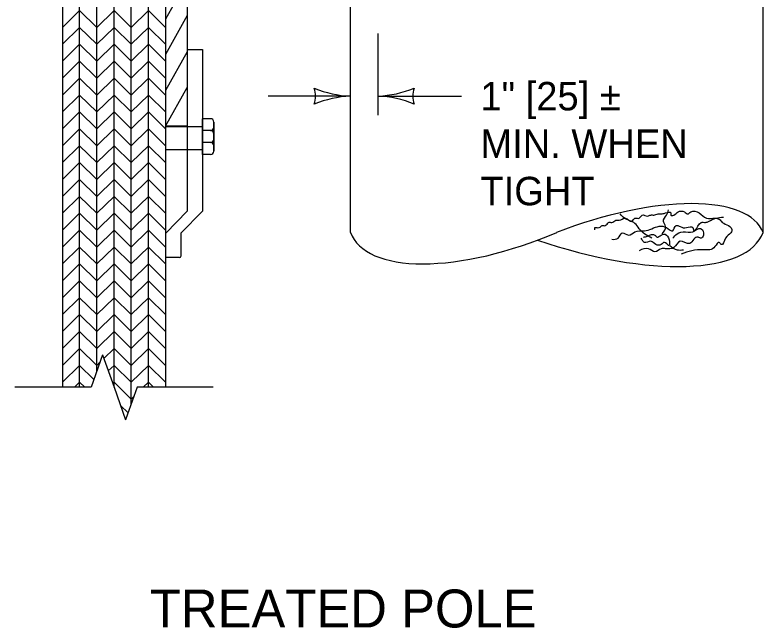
# Model space of a CAD drawing. Extents: x 49991.4 to 50021, y 49987.6 to 50011.4.
# Drawn here: x 50010.201 to 50011.777, y 49992.457 to 49993.749 of the extents above; entities that cross this region are included whole.
import ezdxf

# ---------------------------------------------------------------- set-up
doc = ezdxf.new("R2010")
doc.units = 0
for name, color, linetype in [('Level 1', 7, 'Continuous'), ('Level 2', 7, 'Continuous'), ('Level 3', 7, 'Continuous'), ('Level 4', 7, 'Continuous'), ('Level 6', 7, 'Continuous')]:
    doc.layers.add(name, color=color, linetype=linetype)

msp = doc.modelspace()

# ---------------------------------------------------------------- linework, layer by layer
at = {"layer": 'Level 1'}
for p, q in [((50010.3733, 49992.9985), (50010.3733, 49995.0328)), ((50010.3009, 49994.9995), (50010.3009, 49992.9641)), ((50010.3371, 49992.9641), (50010.3371, 49994.9995)), ((50010.4095, 49992.9641), (50010.4095, 49995.0012)), ((50010.4819, 49992.9641), (50010.4819, 49994.9995)), ((50010.5181, 49994.9995), (50010.5181, 49992.9641)), ((50010.4457, 49992.9286), (50010.4457, 49994.9629)), ((50010.9074, 49993.2905), (50010.9074, 49994.7281)), ((50010.3733, 49992.9985), (50010.3733, 49994.5768)), ((50010.4457, 49992.9641), (50010.4457, 49994.5768)), ((50010.5644, 49993.6762), (50010.5644, 49994.0098)), ((50010.5186, 49993.7404), (50010.5651, 49993.8234)), ((50010.3009, 49993.7224), (50010.3371, 49993.758)), ((50010.3733, 49993.7224), (50010.3371, 49993.758)), ((50010.3733, 49993.7224), (50010.4095, 49993.758)), ((50010.4457, 49993.7224), (50010.4095, 49993.758)), ((50010.4457, 49993.7224), (50010.4819, 49993.758)), ((50010.5181, 49993.7224), (50010.4819, 49993.758)), ((50010.5186, 49993.6657), (50010.5646, 49993.7479)), ((50011.7765, 49993.2905), (50011.7765, 49993.7455)), ((50010.3009, 49993.6868), (50010.3371, 49993.7224)), ((50010.3733, 49993.6868), (50010.3371, 49993.7224)), ((50010.3733, 49993.6868), (50010.4095, 49993.7224)), ((50010.4457, 49993.6868), (50010.4095, 49993.7224)), ((50010.4457, 49993.6868), (50010.4819, 49993.7224)), ((50010.5181, 49993.6868), (50010.4819, 49993.7224)), ((50010.3009, 49993.6512), (50010.3371, 49993.6868)), ((50010.3733, 49993.6512), (50010.3371, 49993.6868)), ((50010.3733, 49993.6512), (50010.4095, 49993.6868)), ((50010.4457, 49993.6512), (50010.4095, 49993.6868)), ((50010.4457, 49993.6512), (50010.4819, 49993.6868)), ((50010.5181, 49993.6512), (50010.4819, 49993.6868)), ((50010.5184, 49993.5901), (50010.564, 49993.6715)), ((50010.5636, 49993.6762), (50010.5636, 49993.3914)), ((50010.5644, 49993.6762), (50010.5957, 49993.6762)), ((50010.5957, 49993.6762), (50010.5957, 49993.3914)), ((50010.3009, 49993.6156), (50010.3371, 49993.6512)), ((50010.3733, 49993.6156), (50010.3371, 49993.6512)), ((50010.3733, 49993.6156), (50010.4095, 49993.6512)), ((50010.4457, 49993.6156), (50010.4095, 49993.6512)), ((50010.4457, 49993.6156), (50010.4819, 49993.6512)), ((50010.5181, 49993.6156), (50010.4819, 49993.6512)), ((50010.3009, 49993.58), (50010.3371, 49993.6156)), ((50010.3733, 49993.58), (50010.3371, 49993.6156)), ((50010.3733, 49993.58), (50010.4095, 49993.6156)), ((50010.4457, 49993.58), (50010.4095, 49993.6156)), ((50010.4457, 49993.58), (50010.4819, 49993.6156)), ((50010.5181, 49993.58), (50010.4819, 49993.6156)), ((50010.5181, 49993.5146), (50010.5634, 49993.5955)), ((50010.3009, 49993.5444), (50010.3371, 49993.58)), ((50010.3733, 49993.5444), (50010.3371, 49993.58)), ((50010.3733, 49993.5444), (50010.4095, 49993.58)), ((50010.4457, 49993.5444), (50010.4095, 49993.58)), ((50010.4457, 49993.5444), (50010.4819, 49993.58)), ((50010.5181, 49993.5444), (50010.4819, 49993.58)), ((50010.3009, 49993.5088), (50010.3371, 49993.5444)), ((50010.3733, 49993.5088), (50010.3371, 49993.5444)), ((50010.3733, 49993.5088), (50010.4095, 49993.5444)), ((50010.4457, 49993.5088), (50010.4095, 49993.5444)), ((50010.4457, 49993.5088), (50010.4819, 49993.5444)), ((50010.5181, 49993.5088), (50010.4819, 49993.5444)), ((50010.5956, 49993.5301), (50010.5956, 49993.4546)), ((50010.6125, 49993.5301), (50010.5956, 49993.5301)), ((50010.5959, 49993.4546), (50010.5959, 49993.5301)), ((50010.6128, 49993.5301), (50010.5962, 49993.5301)), ((50010.6196, 49993.5231), (50010.6196, 49993.4616)), ((50010.6199, 49993.4616), (50010.6199, 49993.5231)), ((50010.3009, 49993.4732), (50010.3371, 49993.5088)), ((50010.3733, 49993.4732), (50010.3371, 49993.5088)), ((50010.3733, 49993.4732), (50010.4095, 49993.5088)), ((50010.4457, 49993.4732), (50010.4095, 49993.5088)), ((50010.4457, 49993.4732), (50010.4819, 49993.5088)), ((50010.5181, 49993.4732), (50010.4819, 49993.5088)), ((50010.5181, 49993.5151), (50010.5636, 49993.5151)), ((50010.6196, 49993.5049), (50010.5956, 49993.5049)), ((50010.6199, 49993.5049), (50010.5959, 49993.5049)), ((50010.3009, 49993.4376), (50010.3371, 49993.4732)), ((50010.3733, 49993.4376), (50010.3371, 49993.4732)), ((50010.3733, 49993.4376), (50010.4095, 49993.4732)), ((50010.4457, 49993.4376), (50010.4095, 49993.4732)), ((50010.4457, 49993.4376), (50010.4819, 49993.4732)), ((50010.5181, 49993.4376), (50010.4819, 49993.4732)), ((50010.6196, 49993.4798), (50010.5956, 49993.4798)), ((50010.6199, 49993.4798), (50010.5959, 49993.4798)), ((50010.6128, 49993.4546), (50010.5959, 49993.4546)), ((50010.6125, 49993.4546), (50010.5959, 49993.4546)), ((50010.3009, 49993.402), (50010.3371, 49993.4376)), ((50010.3733, 49993.402), (50010.3371, 49993.4376)), ((50010.3733, 49993.402), (50010.4095, 49993.4376)), ((50010.4457, 49993.402), (50010.4095, 49993.4376)), ((50010.4457, 49993.402), (50010.4819, 49993.4376)), ((50010.5181, 49993.402), (50010.4819, 49993.4376)), ((50010.3009, 49993.3664), (50010.3371, 49993.402)), ((50010.3733, 49993.3664), (50010.3371, 49993.402)), ((50010.3733, 49993.3664), (50010.4095, 49993.402)), ((50010.4457, 49993.3664), (50010.4095, 49993.402)), ((50010.4457, 49993.3664), (50010.4819, 49993.402)), ((50010.5181, 49993.3664), (50010.4819, 49993.402)), ((50010.5636, 49993.3914), (50010.5636, 49993.3352)), ((50010.5957, 49993.3914), (50010.5957, 49993.3352)), ((50010.3009, 49993.3308), (50010.3371, 49993.3664)), ((50010.3733, 49993.3308), (50010.3371, 49993.3664)), ((50010.3733, 49993.3308), (50010.4095, 49993.3664)), ((50010.4457, 49993.3308), (50010.4095, 49993.3664)), ((50010.4457, 49993.3308), (50010.4819, 49993.3664)), ((50010.5181, 49993.3308), (50010.4819, 49993.3664)), ((50010.5185, 49993.2892), (50010.5636, 49993.3352)), ((50010.5506, 49993.2892), (50010.5957, 49993.3352)), ((50010.3009, 49993.2952), (50010.3371, 49993.3308)), ((50010.3733, 49993.2952), (50010.3371, 49993.3308)), ((50010.3733, 49993.2952), (50010.4095, 49993.3308)), ((50010.4457, 49993.2952), (50010.4095, 49993.3308)), ((50010.4457, 49993.2952), (50010.4819, 49993.3308)), ((50010.5181, 49993.2952), (50010.4819, 49993.3308)), ((50010.3009, 49993.2596), (50010.3371, 49993.2952)), ((50010.3733, 49993.2596), (50010.3371, 49993.2952)), ((50010.3733, 49993.2596), (50010.4095, 49993.2952)), ((50010.4457, 49993.2596), (50010.4095, 49993.2952)), ((50010.4457, 49993.2596), (50010.4819, 49993.2952)), ((50010.5181, 49993.2596), (50010.4819, 49993.2952)), ((50010.5506, 49993.2892), (50010.5506, 49993.2409)), ((50010.3009, 49993.224), (50010.3371, 49993.2596)), ((50010.3733, 49993.224), (50010.3371, 49993.2596)), ((50010.3733, 49993.224), (50010.4095, 49993.2596)), ((50010.4457, 49993.224), (50010.4095, 49993.2596)), ((50010.4457, 49993.224), (50010.4819, 49993.2596)), ((50010.5181, 49993.224), (50010.4819, 49993.2596)), ((50010.5471, 49993.2373), (50010.5185, 49993.2373)), ((50010.3009, 49993.1884), (50010.3371, 49993.224)), ((50010.3733, 49993.1884), (50010.3371, 49993.224)), ((50010.3733, 49993.1884), (50010.4095, 49993.224)), ((50010.4457, 49993.1884), (50010.4095, 49993.224)), ((50010.4457, 49993.1884), (50010.4819, 49993.224)), ((50010.5181, 49993.1884), (50010.4819, 49993.224)), ((50010.3009, 49993.1528), (50010.3371, 49993.1884)), ((50010.3733, 49993.1528), (50010.3371, 49993.1884)), ((50010.3733, 49993.1528), (50010.4095, 49993.1884)), ((50010.4457, 49993.1528), (50010.4095, 49993.1884)), ((50010.4457, 49993.1528), (50010.4819, 49993.1884)), ((50010.5181, 49993.1528), (50010.4819, 49993.1884)), ((50010.3009, 49993.1172), (50010.3371, 49993.1528)), ((50010.3733, 49993.1172), (50010.3371, 49993.1528)), ((50010.3733, 49993.1172), (50010.4095, 49993.1528)), ((50010.4457, 49993.1172), (50010.4095, 49993.1528)), ((50010.4457, 49993.1172), (50010.4819, 49993.1528)), ((50010.5181, 49993.1172), (50010.4819, 49993.1528)), ((50010.3009, 49993.0816), (50010.3371, 49993.1172)), ((50010.3733, 49993.0816), (50010.3371, 49993.1172)), ((50010.3733, 49993.0816), (50010.4095, 49993.1172)), ((50010.4457, 49993.0816), (50010.4095, 49993.1172)), ((50010.4457, 49993.0816), (50010.4819, 49993.1172)), ((50010.5181, 49993.0816), (50010.4819, 49993.1172)), ((50010.3009, 49993.046), (50010.3371, 49993.0816)), ((50010.3733, 49993.046), (50010.3371, 49993.0816)), ((50010.3733, 49993.046), (50010.4095, 49993.0816)), ((50010.4457, 49993.046), (50010.4095, 49993.0816)), ((50010.4457, 49993.046), (50010.4819, 49993.0816)), ((50010.5181, 49993.046), (50010.4819, 49993.0816)), ((50010.3009, 49993.0104), (50010.3371, 49993.046)), ((50010.3733, 49993.0104), (50010.3371, 49993.046)), ((50010.3881, 49993.025), (50010.4095, 49993.046)), ((50010.4457, 49993.0104), (50010.4095, 49993.046)), ((50010.4457, 49993.0104), (50010.4819, 49993.046)), ((50010.5181, 49993.0104), (50010.4819, 49993.046)), ((50010.3733, 49993.0104), (50010.3798, 49993.0168)), ((50010.3009, 49992.9748), (50010.3371, 49993.0104)), ((50010.3671, 49992.9809), (50010.3371, 49993.0104)), ((50010.3975, 49992.9986), (50010.4095, 49993.0104)), ((50010.4457, 49992.9748), (50010.4095, 49993.0104)), ((50010.4457, 49992.9748), (50010.4819, 49993.0104)), ((50010.5181, 49992.9748), (50010.4819, 49993.0104)), ((50010.3262, 49992.9641), (50010.3371, 49992.9748)), ((50010.348, 49992.9641), (50010.3371, 49992.9748)), ((50010.4068, 49992.9722), (50010.4095, 49992.9748)), ((50010.4457, 49992.9392), (50010.4095, 49992.9748)), ((50010.471, 49992.9641), (50010.4819, 49992.9748)), ((50010.4928, 49992.9641), (50010.4819, 49992.9748)), ((50010.4457, 49992.9392), (50010.4515, 49992.9449)), ((50010.4391, 49992.9101), (50010.4234, 49992.9256))]:
    msp.add_line(p, q, dxfattribs=at)
for centre, radius, start, end in [((50010.6125, 49993.5231), 0.00703, 0, 90), ((50010.6128, 49993.5231), 0.00703, 0, 90), ((50010.6125, 49993.512), 0.00703, 270, 0), ((50010.6125, 49993.4979), 0.00703, 0, 90), ((50010.6128, 49993.512), 0.00703, 270, 0), ((50010.6128, 49993.4979), 0.00703, 0, 90), ((50010.6125, 49993.4868), 0.00703, 270, 0), ((50010.6125, 49993.4727), 0.00703, 0, 90), ((50010.6128, 49993.4868), 0.00703, 270, 0), ((50010.6128, 49993.4727), 0.00703, 0, 90), ((50010.6125, 49993.4616), 0.00703, 270, 0), ((50010.6128, 49993.4616), 0.00703, 270, 0), ((50010.5471, 49993.2409), 0.00352, 270, 0)]:
    msp.add_arc(centre, radius, start, end, dxfattribs=at)
for centre, major_axis, ratio, start_param, end_param in [((50011.3985, 49993.1442), (0.378, 0.1463), 0.387082, 0, 1.57099), ((50011.2773, 49993.4465), (-0.3686, -0.1593), 0.420526, 6.263117, 7.847357), ((50011.351, 49993.4409), (0.4255, -0.1504), 0.384401, 4.732347, 6.283185)]:
    msp.add_ellipse(centre, major_axis=major_axis, ratio=ratio, start_param=start_param, end_param=end_param, dxfattribs=at)
for points in [[(50011.4224, 49993.296), (50011.4224, 49993.3005), (50011.4313, 49993.3005), (50011.4379, 49993.3049), (50011.4446, 49993.3049), (50011.4512, 49993.3116), (50011.4579, 49993.3116), (50011.4668, 49993.316), (50011.4734, 49993.316), (50011.4867, 49993.3204), (50011.5, 49993.3138), (50011.5067, 49993.3204), (50011.5155, 49993.3204), (50011.5222, 49993.3271), (50011.5333, 49993.3249), (50011.5399, 49993.3271), (50011.5466, 49993.3271), (50011.5555, 49993.3293), (50011.5621, 49993.3293), (50011.571, 49993.3315), (50011.5821, 49993.3315), (50011.5821, 49993.3271), (50011.5887, 49993.3271), (50011.5976, 49993.3337), (50011.6109, 49993.3337), (50011.6176, 49993.3293), (50011.6242, 49993.3337), (50011.6419, 49993.3315), (50011.6575, 49993.3204), (50011.6752, 49993.3204), (50011.6841, 49993.3182), (50011.6907, 49993.3116), (50011.704, 49993.3049), (50011.7107, 49993.2938), (50011.7085, 49993.2894), (50011.6974, 49993.2783), (50011.6885, 49993.265), (50011.6841, 49993.2694), (50011.6752, 49993.2606), (50011.6641, 49993.2539), (50011.6508, 49993.2539), (50011.6264, 49993.2517), (50011.6043, 49993.245)], [(50011.5643, 49993.2872), (50011.571, 49993.3027), (50011.5666, 49993.3138), (50011.5732, 49993.3271), (50011.5776, 49993.3382)], [(50011.5422, 49993.2783), (50011.5155, 49993.2983), (50011.5067, 49993.3094), (50011.4845, 49993.3204), (50011.4756, 49993.3293)], [(50011.5865, 49993.2783), (50011.5954, 49993.2872), (50011.6131, 49993.2916), (50011.6331, 49993.2938), (50011.6464, 49993.3116), (50011.6553, 49993.3116), (50011.6619, 49993.3138), (50011.6774, 49993.3204), (50011.693, 49993.3227)], [(50011.4579, 49993.2761), (50011.4712, 49993.2783), (50011.4801, 49993.2894), (50011.4934, 49993.285), (50011.5067, 49993.2916), (50011.5266, 49993.2938), (50011.5422, 49993.2983), (50011.5732, 49993.3005), (50011.5865, 49993.2938), (50011.5932, 49993.3049), (50011.602, 49993.3027), (50011.6153, 49993.3005), (50011.6286, 49993.3005), (50011.6309, 49993.2938), (50011.6397, 49993.2983), (50011.6464, 49993.2983), (50011.6508, 49993.285), (50011.6464, 49993.2783), (50011.6397, 49993.2805), (50011.6309, 49993.2761), (50011.622, 49993.2672), (50011.602, 49993.2717), (50011.5887, 49993.2584), (50011.571, 49993.2561), (50011.5621, 49993.2561), (50011.5488, 49993.2495), (50011.5355, 49993.2561), (50011.5155, 49993.2517)], [(50011.5244, 49993.2805), (50011.5333, 49993.2827), (50011.5488, 49993.285), (50011.5532, 49993.2805), (50011.5621, 49993.285), (50011.5732, 49993.285), (50011.5776, 49993.2628), (50011.5688, 49993.2694), (50011.5621, 49993.265), (50011.551, 49993.265), (50011.5399, 49993.2717), (50011.5266, 49993.2694), (50011.5222, 49993.2739), (50011.52, 49993.2783)], [(50011.5799, 49993.2628), (50011.5954, 49993.2539), (50011.6087, 49993.2539)]]:
    msp.add_spline(points, degree=3, dxfattribs=at)
at = {"layer": 'Level 3'}
for p, q in [((50010.9656, 49993.5376), (50010.9656, 49993.7094)), ((50010.9074, 49993.5776), (50010.734, 49993.5776)), ((50010.9656, 49993.5776), (50011.1412, 49993.5776))]:
    msp.add_line(p, q, dxfattribs=at)
for centre, radius, start, end in [((50010.9166, 49993.7997), 0.2223, 247.456, 267.6395), ((50010.7792, 49993.5776), 0.0548, 342.1388, 17.8612), ((50010.9541, 49993.8103), 0.233, 272.8273, 292.0772), ((50011.0938, 49993.5776), 0.0548, 162.1388, 197.8612), ((50010.9189, 49993.3449), 0.233, 92.8273, 112.0772), ((50010.9564, 49993.3555), 0.2223, 67.456, 87.6395)]:
    msp.add_arc(centre, radius, start, end, dxfattribs=at)
at = {"layer": 'Level 4'}
for p, q in [((50011.7765, 49993.7455), (50011.7765, 49994.3075)), ((50010.5959, 49993.5126), (50010.5193, 49993.5126)), ((50010.5959, 49993.4647), (50010.5193, 49993.4647))]:
    msp.add_line(p, q, dxfattribs=at)
at = {"layer": 'Level 6'}
for p, q in [((50010.3854, 49993.0326), (50010.3611, 49992.9641)), ((50010.3854, 49993.0326), (50010.4097, 49992.9641)), ((50010.3611, 49992.9641), (50010.2009, 49992.9641)), ((50010.4097, 49992.9641), (50010.434, 49992.8956)), ((50010.4583, 49992.9641), (50010.434, 49992.8956)), ((50010.6181, 49992.9641), (50010.4583, 49992.9641))]:
    msp.add_line(p, q, dxfattribs=at)

# ---------------------------------------------------------------- texts
at = {"layer": 'Level 2'}
for s, height, p in [('1" [25] ±', 0.06, (50011.1812, 49993.5476)), ('MIN. WHEN ', 0.06, (50011.1812, 49993.4476)), ('TIGHT', 0.06, (50011.1812, 49993.3476)), ('TREATED POLE', 0.08, (50010.4851, 49992.4581))]:
    msp.add_text(s, height=height, dxfattribs=at).set_placement(p)

doc.saveas('drawing.dxf')
